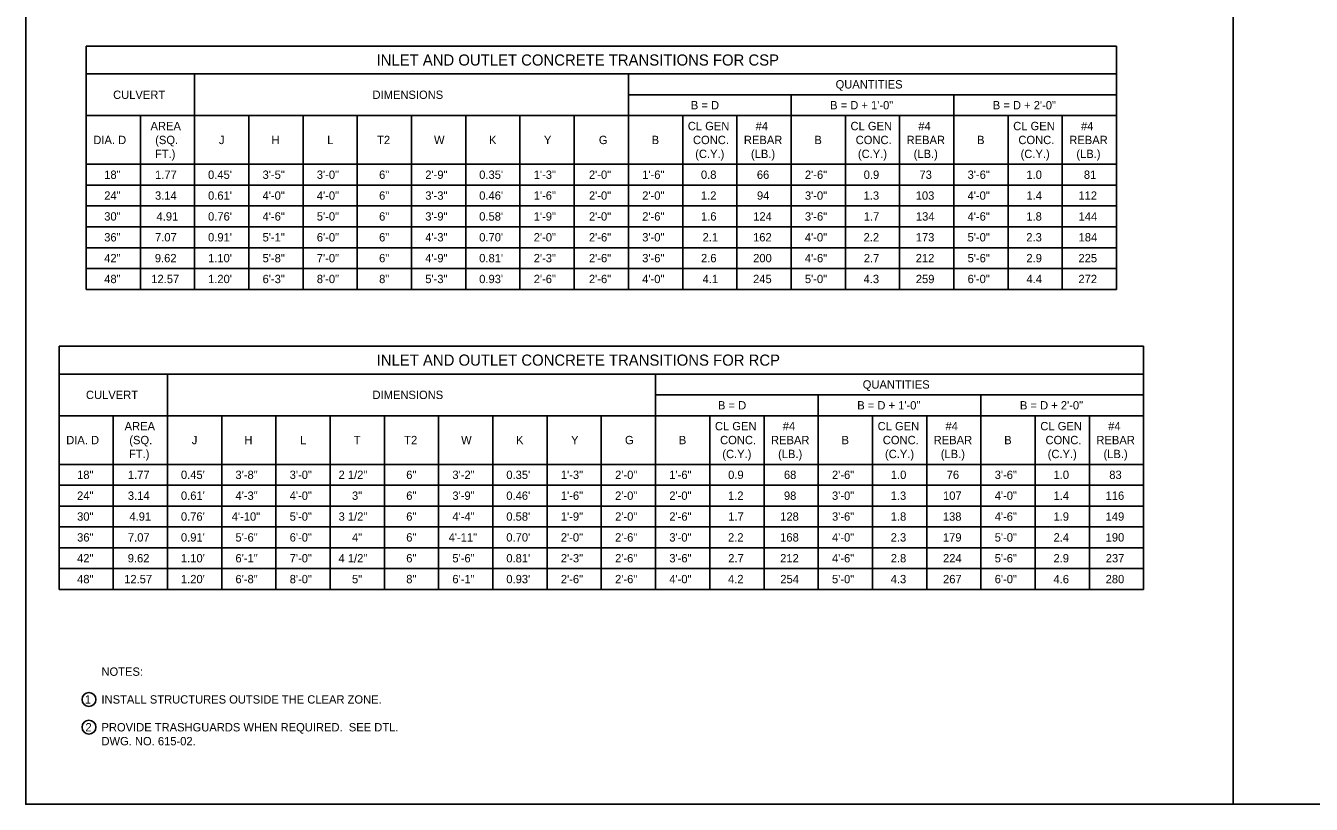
# Model space of a CAD drawing. Extents: x 49991.4 to 50043, y 49987.6 to 50011.4.
# Drawn here: x 49999.38 to 50008.63, y 49987.8 to 49993.4 of the extents above; entities that cross this region are included whole.
import ezdxf

# ---------------------------------------------------------------- set-up
doc = ezdxf.new("R2010")
doc.units = 0
doc.layers.add('Level 1', color=7, linetype='Continuous')
doc.layers.add('Level 2', color=7, linetype='Continuous')

msp = doc.modelspace()

# ---------------------------------------------------------------- linework, layer by layer
at = {"layer": 'Level 1'}
msp.add_line((50008.0668, 49998.9992), (50008.0668, 49987.7988), dxfattribs=at)
msp.add_lwpolyline([(49999.3835, 49998.9992), (50016.7501, 49998.9992), (50016.7501, 49987.7988), (49999.3835, 49987.7988)], close=True, dxfattribs=at)
at = {"layer": 'Level 2'}
for p, q in [((49999.818, 49993.2523), (50007.228, 49993.2523)), ((49999.818, 49993.0523), (50007.228, 49993.0523)), ((50003.718, 49992.9023), (50007.228, 49992.9023)), ((49999.818, 49992.7523), (50007.228, 49992.7523)), ((49999.818, 49992.4023), (50007.228, 49992.4023)), ((49999.818, 49992.2523), (50007.228, 49992.2523)), ((49999.818, 49992.1023), (50007.228, 49992.1023)), ((49999.818, 49991.9523), (50007.228, 49991.9523)), ((49999.818, 49991.8023), (50007.228, 49991.8023)), ((49999.818, 49991.6523), (50007.228, 49991.6523)), ((49999.818, 49991.5023), (50007.228, 49991.5023))]:
    msp.add_line(p, q, dxfattribs=at)
for points in [[(49999.818, 49991.5023), (49999.818, 49993.2523)], [(50007.228, 49991.5023), (50007.228, 49993.2523)], [(50000.598, 49991.5023), (50000.598, 49993.0523)], [(50003.718, 49991.5023), (50003.718, 49993.0523)], [(50004.888, 49991.5023), (50004.888, 49992.9023)], [(50006.058, 49991.5023), (50006.058, 49992.9023)], [(50000.208, 49991.5023), (50000.208, 49992.7523)], [(50000.988, 49991.5023), (50000.988, 49992.7523)], [(50001.378, 49991.5023), (50001.378, 49992.7523)], [(50001.768, 49991.5023), (50001.768, 49992.7523)], [(50002.158, 49991.5023), (50002.158, 49992.7523)], [(50002.548, 49991.5023), (50002.548, 49992.7523)], [(50002.938, 49991.5023), (50002.938, 49992.7523)], [(50003.328, 49991.5023), (50003.328, 49992.7523)], [(50004.108, 49991.5023), (50004.108, 49992.7523)], [(50004.498, 49991.5023), (50004.498, 49992.7523)], [(50005.278, 49991.5023), (50005.278, 49992.7523)], [(50005.668, 49991.5023), (50005.668, 49992.7523)], [(50006.448, 49991.5023), (50006.448, 49992.7523)], [(50006.838, 49991.5023), (50006.838, 49992.7523)], [(49999.623, 49989.3437), (49999.623, 49991.0937)], [(49999.623, 49991.0937), (50007.423, 49991.0937)], [(50007.423, 49989.3437), (50007.423, 49991.0937)], [(49999.623, 49990.8937), (50007.423, 49990.8937)], [(50000.403, 49989.3437), (50000.403, 49990.8937)], [(50003.913, 49989.3437), (50003.913, 49990.8937)], [(50003.913, 49990.7437), (50007.423, 49990.7437)], [(50005.083, 49989.3437), (50005.083, 49990.7437)], [(50006.253, 49989.3437), (50006.253, 49990.7437)], [(49999.623, 49990.5937), (50007.423, 49990.5937)], [(50000.013, 49989.3437), (50000.013, 49990.5937)], [(50000.793, 49989.3437), (50000.793, 49990.5937)], [(50001.183, 49989.3437), (50001.183, 49990.5937)], [(50001.573, 49989.3437), (50001.573, 49990.5937)], [(50001.963, 49989.3437), (50001.963, 49990.5937)], [(50002.353, 49989.3437), (50002.353, 49990.5937)], [(50002.743, 49989.3437), (50002.743, 49990.5937)], [(50003.133, 49989.3437), (50003.133, 49990.5937)], [(50003.523, 49989.3437), (50003.523, 49990.5937)], [(50004.303, 49989.3437), (50004.303, 49990.5937)], [(50004.693, 49989.3437), (50004.693, 49990.5937)], [(50005.473, 49989.3437), (50005.473, 49990.5937)], [(50005.863, 49989.3437), (50005.863, 49990.5937)], [(50006.643, 49989.3437), (50006.643, 49990.5937)], [(50007.033, 49989.3437), (50007.033, 49990.5937)], [(49999.623, 49990.2437), (50007.423, 49990.2437)], [(49999.623, 49990.0937), (50007.423, 49990.0937)], [(49999.623, 49989.9437), (50007.423, 49989.9437)], [(49999.623, 49989.7937), (50007.423, 49989.7937)], [(49999.623, 49989.6437), (50007.423, 49989.6437)], [(49999.623, 49989.4937), (50007.423, 49989.4937)], [(49999.623, 49989.3437), (50007.423, 49989.3437)]]:
    msp.add_lwpolyline(points, dxfattribs=at)
for centre in [(49999.8383, 49988.553), (49999.8383, 49988.353)]:
    msp.add_circle(centre, 0.05, dxfattribs=at)

# ---------------------------------------------------------------- texts
for s, height, p in [('INLET AND OUTLET CONCRETE TRANSITIONS FOR CSP', 0.08, (50001.9063, 49993.1123)), ('QUANTITIES', 0.06, (50005.2077, 49992.9473)), ('CULVERT', 0.06, (50000.012, 49992.8723)), ('DIMENSIONS', 0.06, (50001.8775, 49992.8723)), ('B = D', 0.06, (50004.1668, 49992.7973)), ('B = D + 1\'-0"', 0.06, (50005.1682, 49992.7973)), ('B = D + 2\'-0"', 0.06, (50006.3382, 49992.7973)), ('AREA', 0.06, (50000.2811, 49992.6473)), ('CL GEN', 0.06, (50004.1449, 49992.6473)), ('#4', 0.06, (50004.6327, 49992.6473)), ('CL GEN', 0.06, (50005.3149, 49992.6473)), ('#4', 0.06, (50005.8027, 49992.6473)), ('CL GEN', 0.06, (50006.4849, 49992.6473)), ('#4', 0.06, (50006.9727, 49992.6473)), ('DIA. D', 0.06, (49999.8698, 49992.5473)), ('(SQ. ', 0.06, (50000.3148, 49992.5473)), ('J', 0.06, (50000.7727, 49992.5473)), ('H', 0.06, (50001.151, 49992.5473)), ('L', 0.06, (50001.5518, 49992.5473)), ('T2', 0.06, (50001.9105, 49992.5473)), ('W', 0.06, (50002.3198, 49992.5473)), ('K', 0.06, (50002.7149, 49992.5473)), ('Y', 0.06, (50003.1103, 49992.5473)), ('G', 0.06, (50003.5053, 49992.5473)), ('B', 0.06, (50003.8853, 49992.5473)), ('CONC.', 0.06, (50004.1822, 49992.5473)), ('REBAR', 0.06, (50004.5482, 49992.5473)), ('B', 0.06, (50005.0553, 49992.5473)), ('CONC.', 0.06, (50005.3522, 49992.5473)), ('REBAR', 0.06, (50005.7182, 49992.5473)), ('B', 0.06, (50006.2253, 49992.5473)), ('CONC.', 0.06, (50006.5222, 49992.5473)), ('REBAR', 0.06, (50006.8882, 49992.5473)), ('FT.)', 0.06, (50000.313, 49992.4473)), ('(C.Y.)', 0.06, (50004.198, 49992.4473)), ('(LB.)', 0.06, (50004.5992, 49992.4473)), ('(C.Y.)', 0.06, (50005.368, 49992.4473)), ('(LB.)', 0.06, (50005.7692, 49992.4473)), ('(C.Y.)', 0.06, (50006.538, 49992.4473)), ('(LB.)', 0.06, (50006.9392, 49992.4473)), ('18"', 0.06, (49999.9481, 49992.2973)), ('1.77', 0.06, (50000.3135, 49992.2973)), ("0.45'", 0.06, (50000.6948, 49992.2973)), ('3\'-5"', 0.06, (50001.0869, 49992.2973)), ('3\'-0"', 0.06, (50001.4769, 49992.2973)), ('6"', 0.06, (50001.925, 49992.2973)), ('2\'-9"', 0.06, (50002.2569, 49992.2973)), ("0.35'", 0.06, (50002.6448, 49992.2973)), ('1\'-3"', 0.06, (50003.0369, 49992.2973)), ('2\'-0"', 0.06, (50003.434, 49992.2973)), ('1\'-6"', 0.06, (50003.8169, 49992.2973)), ('0.8', 0.06, (50004.2393, 49992.2973)), ('66', 0.06, (50004.6416, 49992.2973)), ('2\'-6"', 0.06, (50004.9869, 49992.2973)), ('0.9', 0.06, (50005.4098, 49992.2973)), ('73', 0.06, (50005.8109, 49992.2973)), ('3\'-6"', 0.06, (50006.1569, 49992.2973)), ('1.0', 0.06, (50006.5799, 49992.2973)), ('81', 0.06, (50006.9931, 49992.2973)), ('24"', 0.06, (49999.9481, 49992.1473)), ('3.14', 0.06, (50000.3133, 49992.1473)), ("0.61'", 0.06, (50000.6948, 49992.1473)), ('4\'-0"', 0.06, (50001.0869, 49992.1473)), ('4\'-0"', 0.06, (50001.4769, 49992.1473)), ('6"', 0.06, (50001.925, 49992.1473)), ('3\'-3"', 0.06, (50002.2569, 49992.1473)), ("0.46'", 0.06, (50002.6448, 49992.1473)), ('1\'-6"', 0.06, (50003.0369, 49992.1473)), ('2\'-0"', 0.06, (50003.434, 49992.1473)), ('2\'-0"', 0.06, (50003.8169, 49992.1473)), ('1.2', 0.06, (50004.2391, 49992.1473)), ('94', 0.06, (50004.6421, 49992.1473)), ('3\'-0"', 0.06, (50004.9869, 49992.1473)), ('1.3', 0.06, (50005.4091, 49992.1473)), ('103', 0.06, (50005.7839, 49992.1473)), ('4\'-0"', 0.06, (50006.1569, 49992.1473)), ('1.4', 0.06, (50006.5803, 49992.1473)), ('112', 0.06, (50006.954, 49992.1473)), ('30"', 0.06, (49999.9481, 49991.9973)), ('4.91', 0.06, (50000.3244, 49991.9973)), ("0.76'", 0.06, (50000.6948, 49991.9973)), ('4\'-6"', 0.06, (50001.0869, 49991.9973)), ('5\'-0"', 0.06, (50001.4769, 49991.9973)), ('6"', 0.06, (50001.925, 49991.9973)), ('3\'-9"', 0.06, (50002.2569, 49991.9973)), ("0.58'", 0.06, (50002.6448, 49991.9973)), ('1\'-9"', 0.06, (50003.0369, 49991.9973)), ('2\'-0"', 0.06, (50003.434, 49991.9973)), ('2\'-6"', 0.06, (50003.8169, 49991.9973)), ('1.6', 0.06, (50004.2398, 49991.9973)), ('124', 0.06, (50004.6152, 49991.9973)), ('3\'-6"', 0.06, (50004.9869, 49991.9973)), ('1.7', 0.06, (50005.4105, 49991.9973)), ('134', 0.06, (50005.7852, 49991.9973)), ('4\'-6"', 0.06, (50006.1569, 49991.9973)), ('1.8', 0.06, (50006.5793, 49991.9973)), ('144', 0.06, (50006.9552, 49991.9973)), ('36"', 0.06, (49999.9481, 49991.8473)), ('7.07', 0.06, (50000.3135, 49991.8473)), ("0.91'", 0.06, (50000.6948, 49991.8473)), ('5\'-1"', 0.06, (50001.0869, 49991.8473)), ('6\'-0"', 0.06, (50001.4769, 49991.8473)), ('6"', 0.06, (50001.925, 49991.8473)), ('4\'-3"', 0.06, (50002.2569, 49991.8473)), ("0.70'", 0.06, (50002.6448, 49991.8473)), ('2\'-0"', 0.06, (50003.0369, 49991.8473)), ('2\'-6"', 0.06, (50003.434, 49991.8473)), ('3\'-0"', 0.06, (50003.8169, 49991.8473)), ('2.1', 0.06, (50004.2513, 49991.8473)), ('162', 0.06, (50004.614, 49991.8473)), ('4\'-0"', 0.06, (50004.9869, 49991.8473)), ('2.2', 0.06, (50005.4091, 49991.8473)), ('173', 0.06, (50005.7839, 49991.8473)), ('5\'-0"', 0.06, (50006.1569, 49991.8473)), ('2.3', 0.06, (50006.5791, 49991.8473)), ('184', 0.06, (50006.9552, 49991.8473)), ('42"', 0.06, (49999.9481, 49991.6973)), ('9.62', 0.06, (50000.3122, 49991.6973)), ("1.10'", 0.06, (50000.6948, 49991.6973)), ('5\'-8"', 0.06, (50001.0869, 49991.6973)), ('7\'-0"', 0.06, (50001.4769, 49991.6973)), ('6"', 0.06, (50001.925, 49991.6973)), ('4\'-9"', 0.06, (50002.2569, 49991.6973)), ("0.81'", 0.06, (50002.6448, 49991.6973)), ('2\'-3"', 0.06, (50003.0369, 49991.6973)), ('2\'-6"', 0.06, (50003.434, 49991.6973)), ('3\'-6"', 0.06, (50003.8169, 49991.6973)), ('2.6', 0.06, (50004.2398, 49991.6973)), ('200', 0.06, (50004.6148, 49991.6973)), ('4\'-6"', 0.06, (50004.9869, 49991.6973)), ('2.7', 0.06, (50005.4105, 49991.6973)), ('212', 0.06, (50005.784, 49991.6973)), ('5\'-6"', 0.06, (50006.1569, 49991.6973)), ('2.9', 0.06, (50006.5798, 49991.6973)), ('225', 0.06, (50006.9542, 49991.6973)), ('48"', 0.06, (49999.9481, 49991.5473)), ('12.57', 0.06, (50000.2866, 49991.5473)), ("1.20'", 0.06, (50000.6948, 49991.5473)), ('6\'-3"', 0.06, (50001.0869, 49991.5473)), ('8\'-0"', 0.06, (50001.4769, 49991.5473)), ('8"', 0.06, (50001.925, 49991.5473)), ('5\'-3"', 0.06, (50002.2569, 49991.5473)), ("0.93'", 0.06, (50002.6448, 49991.5473)), ('2\'-6"', 0.06, (50003.0369, 49991.5473)), ('2\'-6"', 0.06, (50003.434, 49991.5473)), ('4\'-0"', 0.06, (50003.8169, 49991.5473)), ('4.1', 0.06, (50004.2513, 49991.5473)), ('245', 0.06, (50004.6142, 49991.5473)), ('5\'-0"', 0.06, (50004.9869, 49991.5473)), ('4.3', 0.06, (50005.4091, 49991.5473)), ('259', 0.06, (50005.7846, 49991.5473)), ('6\'-0"', 0.06, (50006.1569, 49991.5473)), ('4.4', 0.06, (50006.5803, 49991.5473)), ('272', 0.06, (50006.954, 49991.5473)), ('INLET AND OUTLET CONCRETE TRANSITIONS FOR RCP', 0.08, (50001.9075, 49990.9537)), ('CULVERT', 0.06, (49999.817, 49990.7137)), ('DIMENSIONS', 0.06, (50001.8775, 49990.7137)), ('QUANTITIES', 0.06, (50005.4027, 49990.7887)), ('B = D', 0.06, (50004.3618, 49990.6387)), ('B = D + 1\'-0"', 0.06, (50005.3632, 49990.6387)), ('B = D + 2\'-0"', 0.06, (50006.5332, 49990.6387)), ('AREA', 0.06, (50000.0947, 49990.4887)), ('CL GEN', 0.06, (50004.3399, 49990.4887)), ('#4', 0.06, (50004.8277, 49990.4887)), ('CL GEN', 0.06, (50005.5099, 49990.4887)), ('#4', 0.06, (50005.9977, 49990.4887)), ('CL GEN', 0.06, (50006.6799, 49990.4887)), ('#4', 0.06, (50007.1677, 49990.4887)), ('DIA. D', 0.06, (49999.6748, 49990.3887)), ('(SQ. ', 0.06, (50000.1284, 49990.3887)), ('J', 0.06, (50000.5777, 49990.3887)), ('H', 0.06, (50000.956, 49990.3887)), ('L', 0.06, (50001.3568, 49990.3887)), ('T', 0.06, (50001.742, 49990.3887)), ('T2', 0.06, (50002.1055, 49990.3887)), ('W', 0.06, (50002.5148, 49990.3887)), ('K', 0.06, (50002.9099, 49990.3887)), ('Y', 0.06, (50003.3053, 49990.3887)), ('G', 0.06, (50003.6932, 49990.3887)), ('B', 0.06, (50004.0803, 49990.3887)), ('CONC.', 0.06, (50004.3772, 49990.3887)), ('REBAR', 0.06, (50004.7432, 49990.3887)), ('B', 0.06, (50005.2503, 49990.3887)), ('CONC.', 0.06, (50005.5472, 49990.3887)), ('REBAR', 0.06, (50005.9132, 49990.3887)), ('B', 0.06, (50006.4203, 49990.3887)), ('CONC.', 0.06, (50006.7172, 49990.3887)), ('REBAR', 0.06, (50007.0832, 49990.3887)), ('FT.)', 0.06, (50000.1266, 49990.2887)), ('(C.Y.)', 0.06, (50004.393, 49990.2887)), ('(LB.)', 0.06, (50004.7942, 49990.2887)), ('(C.Y.)', 0.06, (50005.563, 49990.2887)), ('(LB.)', 0.06, (50005.9642, 49990.2887)), ('(C.Y.)', 0.06, (50006.733, 49990.2887)), ('(LB.)', 0.06, (50007.1342, 49990.2887)), ('18"', 0.06, (49999.7531, 49990.1387)), ('1.77', 0.06, (50000.1185, 49990.1387)), ("0.45'", 0.06, (50000.4998, 49990.1387)), ('3\'-8"', 0.06, (50000.8919, 49990.1387)), ('3\'-0"', 0.06, (50001.2819, 49990.1387)), ('2 1/2"', 0.06, (50001.6333, 49990.1387)), ('6"', 0.06, (50002.12, 49990.1387)), ('3\'-2"', 0.06, (50002.4519, 49990.1387)), ("0.35'", 0.06, (50002.8398, 49990.1387)), ('1\'-3"', 0.06, (50003.2319, 49990.1387)), ('2\'-0"', 0.06, (50003.6219, 49990.1387)), ('1\'-6"', 0.06, (50004.0119, 49990.1387)), ('0.9', 0.06, (50004.4348, 49990.1387)), ('68', 0.06, (50004.8361, 49990.1387)), ('2\'-6"', 0.06, (50005.1819, 49990.1387)), ('1.0', 0.06, (50005.6049, 49990.1387)), ('76', 0.06, (50006.0066, 49990.1387)), ('3\'-6"', 0.06, (50006.3519, 49990.1387)), ('1.0', 0.06, (50006.775, 49990.1387)), ('83', 0.06, (50007.1758, 49990.1387)), ('24"', 0.06, (49999.7531, 49989.9887)), ('3.14', 0.06, (50000.1183, 49989.9887)), ("0.61'", 0.06, (50000.4998, 49989.9887)), ('4\'-3"', 0.06, (50000.8919, 49989.9887)), ('4\'-0"', 0.06, (50001.2819, 49989.9887)), ('3"', 0.06, (50001.73, 49989.9887)), ('6"', 0.06, (50002.12, 49989.9887)), ('3\'-9"', 0.06, (50002.4519, 49989.9887)), ("0.46'", 0.06, (50002.8398, 49989.9887)), ('1\'-6"', 0.06, (50003.2319, 49989.9887)), ('2\'-0"', 0.06, (50003.6219, 49989.9887)), ('2\'-0"', 0.06, (50004.0119, 49989.9887)), ('1.2', 0.06, (50004.4341, 49989.9887)), ('98', 0.06, (50004.8361, 49989.9887)), ('3\'-0"', 0.06, (50005.1819, 49989.9887)), ('1.3', 0.06, (50005.6041, 49989.9887)), ('107', 0.06, (50005.9803, 49989.9887)), ('4\'-0"', 0.06, (50006.3519, 49989.9887)), ('1.4', 0.06, (50006.7753, 49989.9887)), ('116', 0.06, (50007.1496, 49989.9887)), ('30"', 0.06, (49999.7531, 49989.8387)), ('4.91', 0.06, (50000.1294, 49989.8387)), ("0.76'", 0.06, (50000.4998, 49989.8387)), ('4\'-10"', 0.06, (50000.865, 49989.8387)), ('5\'-0"', 0.06, (50001.2819, 49989.8387)), ('3 1/2"', 0.06, (50001.6333, 49989.8387)), ('6"', 0.06, (50002.12, 49989.8387)), ('4\'-4"', 0.06, (50002.4519, 49989.8387)), ("0.58'", 0.06, (50002.8398, 49989.8387)), ('1\'-9"', 0.06, (50003.2319, 49989.8387)), ('2\'-0"', 0.06, (50003.6219, 49989.8387)), ('2\'-6"', 0.06, (50004.0119, 49989.8387)), ('1.7', 0.06, (50004.4355, 49989.8387)), ('128', 0.06, (50004.8091, 49989.8387)), ('3\'-6"', 0.06, (50005.1819, 49989.8387)), ('1.8', 0.06, (50005.6043, 49989.8387)), ('138', 0.06, (50005.9791, 49989.8387)), ('4\'-6"', 0.06, (50006.3519, 49989.8387)), ('1.9', 0.06, (50006.7748, 49989.8387)), ('149', 0.06, (50007.1496, 49989.8387)), ('36"', 0.06, (49999.7531, 49989.6887)), ('7.07', 0.06, (50000.1185, 49989.6887)), ("0.91'", 0.06, (50000.4998, 49989.6887)), ('5\'-6"', 0.06, (50000.8919, 49989.6887)), ('6\'-0"', 0.06, (50001.2819, 49989.6887)), ('4"', 0.06, (50001.73, 49989.6887)), ('6"', 0.06, (50002.12, 49989.6887)), ('4\'-11"', 0.06, (50002.425, 49989.6887)), ("0.70'", 0.06, (50002.8398, 49989.6887)), ('2\'-0"', 0.06, (50003.2319, 49989.6887)), ('2\'-6"', 0.06, (50003.6219, 49989.6887)), ('3\'-0"', 0.06, (50004.0119, 49989.6887)), ('2.2', 0.06, (50004.4341, 49989.6887)), ('168', 0.06, (50004.8091, 49989.6887)), ('4\'-0"', 0.06, (50005.1819, 49989.6887)), ('2.3', 0.06, (50005.6041, 49989.6887)), ('179', 0.06, (50005.9796, 49989.6887)), ('5\'-0"', 0.06, (50006.3519, 49989.6887)), ('2.4', 0.06, (50006.7753, 49989.6887)), ('190', 0.06, (50007.1497, 49989.6887)), ('42"', 0.06, (49999.7531, 49989.5387)), ('9.62', 0.06, (50000.1172, 49989.5387)), ("1.10'", 0.06, (50000.4998, 49989.5387)), ('6\'-1"', 0.06, (50000.8919, 49989.5387)), ('7\'-0"', 0.06, (50001.2819, 49989.5387)), ('4 1/2"', 0.06, (50001.6333, 49989.5387)), ('6"', 0.06, (50002.12, 49989.5387)), ('5\'-6"', 0.06, (50002.4519, 49989.5387)), ("0.81'", 0.06, (50002.8398, 49989.5387)), ('2\'-3"', 0.06, (50003.2319, 49989.5387)), ('2\'-6"', 0.06, (50003.6219, 49989.5387)), ('3\'-6"', 0.06, (50004.0119, 49989.5387)), ('2.7', 0.06, (50004.4355, 49989.5387)), ('212', 0.06, (50004.809, 49989.5387)), ('4\'-6"', 0.06, (50005.1819, 49989.5387)), ('2.8', 0.06, (50005.6043, 49989.5387)), ('224', 0.06, (50005.9802, 49989.5387)), ('5\'-6"', 0.06, (50006.3519, 49989.5387)), ('2.9', 0.06, (50006.7748, 49989.5387)), ('237', 0.06, (50007.1503, 49989.5387)), ('48"', 0.06, (49999.7531, 49989.3887)), ('12.57', 0.06, (50000.0916, 49989.3887)), ("1.20'", 0.06, (50000.4998, 49989.3887)), ('6\'-8"', 0.06, (50000.8919, 49989.3887)), ('8\'-0"', 0.06, (50001.2819, 49989.3887)), ('5"', 0.06, (50001.73, 49989.3887)), ('8"', 0.06, (50002.12, 49989.3887)), ('6\'-1"', 0.06, (50002.4519, 49989.3887)), ("0.93'", 0.06, (50002.8398, 49989.3887)), ('2\'-6"', 0.06, (50003.2319, 49989.3887)), ('2\'-6"', 0.06, (50003.6219, 49989.3887)), ('4\'-0"', 0.06, (50004.0119, 49989.3887)), ('4.2', 0.06, (50004.4341, 49989.3887)), ('254', 0.06, (50004.8102, 49989.3887)), ('5\'-0"', 0.06, (50005.1819, 49989.3887)), ('4.3', 0.06, (50005.6041, 49989.3887)), ('267', 0.06, (50005.9803, 49989.3887)), ('6\'-0"', 0.06, (50006.3519, 49989.3887)), ('4.6', 0.06, (50006.7748, 49989.3887)), ('280', 0.06, (50007.1497, 49989.3887)), ('NOTES:', 0.06, (49999.9283, 49988.723)), ('1', 0.06, (49999.8087, 49988.523)), ('INSTALL STRUCTURES OUTSIDE THE CLEAR ZONE.', 0.06, (49999.9283, 49988.523)), ('2', 0.06, (49999.8131, 49988.323)), ('PROVIDE TRASHGUARDS WHEN REQUIRED.  SEE DTL.', 0.06, (49999.9283, 49988.323)), ('DWG. NO. 615-02.', 0.06, (49999.9283, 49988.223))]:
    msp.add_text(s, height=height, dxfattribs=at).set_placement(p)

doc.saveas('drawing.dxf')
